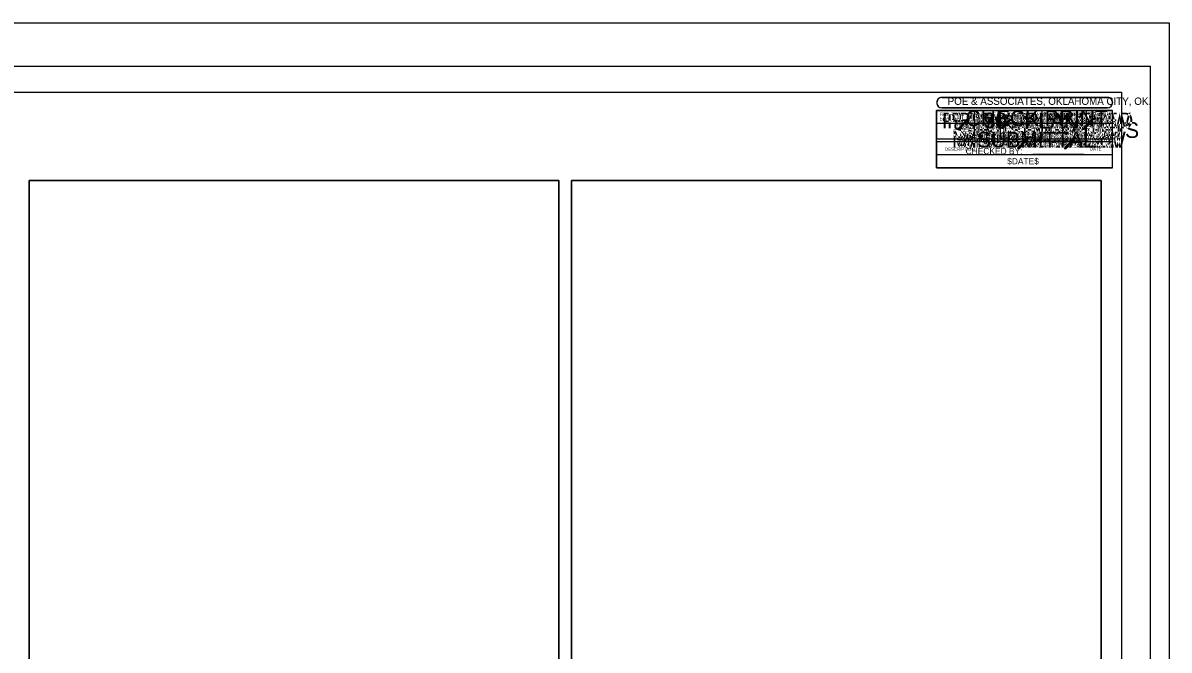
# Model space of a CAD drawing. Extents: x -1.6 to 34.4, y -1.2 to 22.8.
# Drawn here: x 12.44 to 34.36, y 10.82 to 22.82 of the extents above; entities that cross this region are included whole.
import ezdxf

# ---------------------------------------------------------------- set-up
doc = ezdxf.new("R2010")
doc.units = 0
for name, color, linetype in [('PR_OLE_MS_Excel', 7, 'Continuous'), ('SHT_Date_Stamp', 7, 'Continuous'), ('SHT_Plot_Shape_Full', 7, 'Continuous'), ('SHT_Plot_Shape_Half', 7, 'Continuous'), ('SHT_Sheet_Border', 7, 'Continuous'), ('SHT_Stamp_30_Submit', 7, 'Continuous'), ('SHT_Stamp_70_Submit', 7, 'Continuous'), ('SHT_Stamp_90_Submit', 7, 'Continuous'), ('SHT_Stamp_Check_Print', 7, 'Continuous'), ('SHT_Stamp_Est_Inf', 7, 'Continuous'), ('SHT_Stamp_FFR', 7, 'Continuous'), ('SHT_Stamp_Info_Material', 7, 'Continuous'), ('SHT_Stamp_No_Const', 7, 'Continuous'), ('SHT_Stamp_No_Design', 7, 'Continuous'), ('SHT_Stamp_Plan_Hand', 7, 'Continuous'), ('SHT_Stamp_Pre_Plan', 7, 'Continuous'), ('SHT_Stamp_Prop_RW', 7, 'Continuous'), ('SHT_Stamp_Ret_Sub', 7, 'Continuous'), ('SHT_Stamp_Rev_Block', 7, 'Continuous'), ('SHT_Stamp_Rev_Prop_RW', 7, 'Continuous'), ('SHT_Stamp_Rev_Sheet', 7, 'Continuous'), ('SHT_Stamp_RW_Utilities_Meeting', 7, 'Continuous'), ('SHT_Stamp_RW_Utilities_Review', 7, 'Continuous'), ('SHT_Stamp_Send_Comments', 7, 'Continuous')]:
    doc.layers.add(name, color=color, linetype=linetype)

msp = doc.modelspace()

# ---------------------------------------------------------------- linework, layer by layer
at = {"layer": 'PR_OLE_MS_Excel'}
for points in [[(12.56, 19.811), (22.69, 19.811), (22.69, 3.188), (12.56, 3.188)], [(12.56, 3.188), (22.69, 3.188), (22.69, 19.811), (12.56, 19.811)], [(22.93, 19.811), (33.061, 19.811), (33.061, 6.46), (22.93, 6.46)], [(22.93, 6.46), (33.061, 6.46), (33.061, 19.811), (22.93, 19.811)]]:
    msp.add_lwpolyline(points, close=True, dxfattribs=at)
at = {"layer": 'SHT_Plot_Shape_Full'}
msp.add_lwpolyline([(-1.638, 22.825), (34.362, 22.825), (34.362, -1.175), (-1.638, -1.175)], close=True, dxfattribs=at)
at = {"layer": 'SHT_Plot_Shape_Half'}
msp.add_lwpolyline([(0, 22), (34, 22), (34, 0), (0, 0)], close=True, dxfattribs=at)
at = {"layer": 'SHT_Sheet_Border'}
msp.add_lwpolyline([(33.45, 0.5), (1.95, 0.5), (1.95, 21.5), (33.45, 21.5)], close=True, dxfattribs=at)
at = {"layer": 'SHT_Stamp_30_Submit'}
for p, q in [((30.017, 21.4), (33.183, 21.4)), ((29.917, 21.15), (33.283, 21.15)), ((29.917, 20.051), (29.917, 21.15)), ((30.017, 21.2), (33.183, 21.2)), ((33.283, 20.051), (33.283, 21.15)), ((31.161, 20.812), (31.316, 20.984)), ((31.178, 20.812), (31.334, 20.984)), ((31.183, 20.812), (31.339, 20.984)), ((31.191, 20.812), (31.347, 20.984)), ((31.316, 20.984), (31.347, 20.984)), ((31.161, 20.812), (31.191, 20.812)), ((29.917, 20.051), (33.283, 20.051))]:
    msp.add_line(p, q, dxfattribs=at)
for centre, start, end in [((30.018, 21.3), 89.9952, 270), ((33.184, 21.3), 270, 90.0048)]:
    msp.add_arc(centre, 0.1, start, end, dxfattribs=at)
at = {"layer": 'SHT_Stamp_70_Submit'}
for p, q in [((30.017, 21.4), (33.183, 21.4)), ((29.917, 21.15), (33.283, 21.15)), ((29.917, 20.051), (29.917, 21.15)), ((30.017, 21.2), (33.183, 21.2)), ((33.283, 20.051), (33.283, 21.15)), ((31.161, 20.812), (31.316, 20.984)), ((31.178, 20.812), (31.334, 20.984)), ((31.183, 20.812), (31.339, 20.984)), ((31.191, 20.812), (31.347, 20.984)), ((31.316, 20.984), (31.347, 20.984)), ((31.161, 20.812), (31.191, 20.812)), ((29.917, 20.051), (33.283, 20.051))]:
    msp.add_line(p, q, dxfattribs=at)
for centre, start, end in [((30.018, 21.3), 89.9952, 270), ((33.184, 21.3), 270, 90.0048)]:
    msp.add_arc(centre, 0.1, start, end, dxfattribs=at)
at = {"layer": 'SHT_Stamp_90_Submit'}
for p, q in [((30.017, 21.4), (33.183, 21.4)), ((29.917, 21.15), (33.283, 21.15)), ((29.917, 20.051), (29.917, 21.15)), ((30.017, 21.2), (33.183, 21.2)), ((33.283, 20.051), (33.283, 21.15)), ((31.161, 20.812), (31.316, 20.984)), ((31.178, 20.812), (31.334, 20.984)), ((31.183, 20.812), (31.339, 20.984)), ((31.191, 20.812), (31.347, 20.984)), ((31.316, 20.984), (31.347, 20.984)), ((31.161, 20.812), (31.191, 20.812)), ((29.917, 20.051), (33.283, 20.051))]:
    msp.add_line(p, q, dxfattribs=at)
for centre, start, end in [((30.018, 21.3), 89.9952, 270), ((33.184, 21.3), 270, 90.0048)]:
    msp.add_arc(centre, 0.1, start, end, dxfattribs=at)
at = {"layer": 'SHT_Stamp_Check_Print'}
for p, q in [((30.017, 21.4), (33.183, 21.4)), ((29.917, 21.15), (33.283, 21.15)), ((29.917, 20.051), (29.917, 21.15)), ((30.017, 21.2), (33.183, 21.2)), ((33.283, 20.051), (33.283, 21.15)), ((31.759, 20.569), (32.73, 20.569)), ((31.759, 20.313), (32.73, 20.313)), ((29.917, 20.051), (33.283, 20.051))]:
    msp.add_line(p, q, dxfattribs=at)
for centre, start, end in [((30.018, 21.3), 89.9952, 270), ((33.184, 21.3), 270, 90.0048)]:
    msp.add_arc(centre, 0.1, start, end, dxfattribs=at)
at = {"layer": 'SHT_Stamp_Est_Inf'}
for p, q in [((30.017, 21.4), (33.183, 21.4)), ((29.917, 21.15), (33.283, 21.15)), ((29.917, 20.051), (29.917, 21.15)), ((30.017, 21.2), (33.183, 21.2)), ((33.283, 20.051), (33.283, 21.15)), ((29.917, 20.051), (33.283, 20.051))]:
    msp.add_line(p, q, dxfattribs=at)
for centre, start, end in [((30.018, 21.3), 89.9952, 270), ((33.184, 21.3), 270, 90.0048)]:
    msp.add_arc(centre, 0.1, start, end, dxfattribs=at)
at = {"layer": 'SHT_Stamp_FFR'}
for p, q in [((30.017, 21.4), (33.183, 21.4)), ((29.917, 21.15), (33.283, 21.15)), ((29.917, 20.051), (29.917, 21.15)), ((30.017, 21.2), (33.183, 21.2)), ((33.283, 20.051), (33.283, 21.15)), ((29.917, 20.051), (33.283, 20.051))]:
    msp.add_line(p, q, dxfattribs=at)
for centre, start, end in [((30.018, 21.3), 89.9952, 270), ((33.184, 21.3), 270, 90.0048)]:
    msp.add_arc(centre, 0.1, start, end, dxfattribs=at)
at = {"layer": 'SHT_Stamp_Info_Material'}
for p, q in [((30.017, 21.4), (33.183, 21.4)), ((29.917, 21.15), (33.283, 21.15)), ((29.917, 20.051), (29.917, 21.15)), ((30.017, 21.2), (33.183, 21.2)), ((33.283, 20.051), (33.283, 21.15)), ((29.917, 20.051), (33.283, 20.051))]:
    msp.add_line(p, q, dxfattribs=at)
for centre, start, end in [((30.018, 21.3), 89.9952, 270), ((33.184, 21.3), 270, 90.0048)]:
    msp.add_arc(centre, 0.1, start, end, dxfattribs=at)
at = {"layer": 'SHT_Stamp_No_Const'}
for p, q in [((30.017, 21.4), (33.183, 21.4)), ((29.917, 21.15), (33.283, 21.15)), ((29.917, 20.051), (29.917, 21.15)), ((30.017, 21.2), (33.183, 21.2)), ((33.283, 20.051), (33.283, 21.15)), ((29.917, 20.051), (33.283, 20.051))]:
    msp.add_line(p, q, dxfattribs=at)
for centre, start, end in [((30.018, 21.3), 89.9952, 270), ((33.184, 21.3), 270, 90.0048)]:
    msp.add_arc(centre, 0.1, start, end, dxfattribs=at)
at = {"layer": 'SHT_Stamp_No_Design'}
for p, q in [((30.017, 21.4), (33.183, 21.4)), ((29.917, 21.15), (33.283, 21.15)), ((29.917, 20.051), (29.917, 21.15)), ((30.017, 21.2), (33.183, 21.2)), ((33.283, 20.051), (33.283, 21.15)), ((29.917, 20.051), (33.283, 20.051))]:
    msp.add_line(p, q, dxfattribs=at)
for centre, start, end in [((30.018, 21.3), 89.9952, 270), ((33.184, 21.3), 270, 90.0048)]:
    msp.add_arc(centre, 0.1, start, end, dxfattribs=at)
at = {"layer": 'SHT_Stamp_Plan_Hand'}
for p, q in [((30.017, 21.4), (33.183, 21.4)), ((29.917, 21.15), (33.283, 21.15)), ((29.917, 20.051), (29.917, 21.15)), ((30.017, 21.2), (33.183, 21.2)), ((33.283, 20.051), (33.283, 21.15)), ((29.917, 20.051), (33.283, 20.051))]:
    msp.add_line(p, q, dxfattribs=at)
for centre, start, end in [((30.018, 21.3), 89.9952, 270), ((33.184, 21.3), 270, 90.0048)]:
    msp.add_arc(centre, 0.1, start, end, dxfattribs=at)
at = {"layer": 'SHT_Stamp_Pre_Plan'}
for p, q in [((30.017, 21.4), (33.183, 21.4)), ((29.917, 21.15), (33.283, 21.15)), ((29.917, 20.051), (29.917, 21.15)), ((30.017, 21.2), (33.183, 21.2)), ((33.283, 20.051), (33.283, 21.15)), ((29.917, 20.051), (33.283, 20.051))]:
    msp.add_line(p, q, dxfattribs=at)
for centre, start, end in [((30.018, 21.3), 89.9952, 270), ((33.184, 21.3), 270, 90.0048)]:
    msp.add_arc(centre, 0.1, start, end, dxfattribs=at)
at = {"layer": 'SHT_Stamp_Prop_RW'}
for p, q in [((30.017, 21.4), (33.183, 21.4)), ((30.017, 21.4), (33.183, 21.4)), ((29.917, 21.15), (33.283, 21.15)), ((29.917, 20.051), (29.917, 21.15)), ((29.917, 21.15), (33.283, 21.15)), ((29.917, 20.051), (29.917, 21.15)), ((30.017, 21.2), (33.183, 21.2)), ((30.017, 21.2), (33.183, 21.2)), ((33.283, 20.051), (33.283, 21.15)), ((33.283, 20.051), (33.283, 21.15)), ((31.464, 20.423), (31.656, 20.636)), ((31.464, 20.423), (31.656, 20.636)), ((31.486, 20.423), (31.678, 20.636)), ((31.486, 20.423), (31.678, 20.636)), ((31.492, 20.423), (31.684, 20.636)), ((31.492, 20.423), (31.684, 20.636)), ((31.502, 20.423), (31.694, 20.636)), ((31.502, 20.423), (31.694, 20.636)), ((31.656, 20.636), (31.694, 20.636)), ((31.656, 20.636), (31.694, 20.636)), ((31.464, 20.423), (31.502, 20.423)), ((31.464, 20.423), (31.502, 20.423)), ((29.917, 20.051), (33.283, 20.051)), ((29.917, 20.051), (33.283, 20.051))]:
    msp.add_line(p, q, dxfattribs=at)
for centre, start, end in [((30.018, 21.3), 89.9952, 270), ((30.018, 21.3), 89.9952, 270), ((33.184, 21.3), 270, 90.0048), ((33.184, 21.3), 270, 90.0048)]:
    msp.add_arc(centre, 0.1, start, end, dxfattribs=at)
at = {"layer": 'SHT_Stamp_Ret_Sub'}
for p, q in [((30.017, 21.4), (33.183, 21.4)), ((29.917, 21.15), (33.283, 21.15)), ((29.917, 20.051), (29.917, 21.15)), ((30.017, 21.2), (33.183, 21.2)), ((33.283, 20.051), (33.283, 21.15)), ((29.917, 20.051), (33.283, 20.051))]:
    msp.add_line(p, q, dxfattribs=at)
for centre, start, end in [((30.018, 21.3), 89.9952, 270), ((33.184, 21.3), 270, 90.0048)]:
    msp.add_arc(centre, 0.1, start, end, dxfattribs=at)
at = {"layer": 'SHT_Stamp_Rev_Block'}
for p, q in [((33.183, 21.4), (30.018, 21.4)), ((33.283, 21.15), (29.917, 21.15)), ((29.917, 21.15), (29.917, 20.6)), ((33.183, 21.2), (30.018, 21.2)), ((30.633, 21.15), (30.633, 20.6)), ((31.133, 21.15), (31.133, 20.6)), ((31.933, 20.6), (31.933, 21.15)), ((32.333, 20.6), (32.333, 21.15)), ((32.783, 20.6), (32.783, 21.15)), ((33.283, 20.6), (33.283, 21.15)), ((33.283, 20.9), (29.917, 20.9)), ((33.283, 20.6), (29.917, 20.6)), ((33.283, 20.55), (29.917, 20.55)), ((29.917, 20.55), (29.917, 20.05)), ((33.283, 20.05), (33.283, 20.55)), ((33.283, 20.3), (29.917, 20.3)), ((33.283, 20.05), (29.917, 20.05))]:
    msp.add_line(p, q, dxfattribs=at)
for centre, start, end in [((30.018, 21.299), 90, 270), ((33.183, 21.3), 270, 90)]:
    msp.add_arc(centre, 0.1, start, end, dxfattribs=at)
at = {"layer": 'SHT_Stamp_Rev_Prop_RW'}
for p, q in [((30.017, 21.4), (33.183, 21.4)), ((29.917, 21.15), (33.283, 21.15)), ((29.917, 20.051), (29.917, 21.15)), ((30.017, 21.2), (33.183, 21.2)), ((33.283, 20.051), (33.283, 21.15)), ((32.354, 20.42), (32.546, 20.633)), ((32.376, 20.42), (32.568, 20.633)), ((32.383, 20.42), (32.575, 20.633)), ((32.392, 20.42), (32.584, 20.633)), ((32.546, 20.633), (32.584, 20.633)), ((32.354, 20.42), (32.392, 20.42)), ((29.917, 20.051), (33.283, 20.051))]:
    msp.add_line(p, q, dxfattribs=at)
for centre, start, end in [((30.018, 21.3), 89.9952, 270), ((33.184, 21.3), 270, 90.0048)]:
    msp.add_arc(centre, 0.1, start, end, dxfattribs=at)
at = {"layer": 'SHT_Stamp_Rev_Sheet'}
for p, q in [((30.017, 21.4), (33.183, 21.4)), ((29.917, 21.15), (33.283, 21.15)), ((29.917, 20.051), (29.917, 21.15)), ((30.017, 21.2), (33.183, 21.2)), ((33.283, 20.051), (33.283, 21.15)), ((29.917, 20.051), (33.283, 20.051))]:
    msp.add_line(p, q, dxfattribs=at)
for centre, start, end in [((30.018, 21.3), 89.9952, 270), ((33.184, 21.3), 270, 90.0048)]:
    msp.add_arc(centre, 0.1, start, end, dxfattribs=at)
at = {"layer": 'SHT_Stamp_RW_Utilities_Meeting'}
for p, q in [((30.017, 21.4), (33.183, 21.4)), ((29.917, 21.15), (33.283, 21.15)), ((29.917, 20.051), (29.917, 21.15)), ((30.017, 21.2), (33.183, 21.2)), ((33.283, 20.051), (33.283, 21.15)), ((30.319, 20.789), (30.511, 21.003)), ((30.341, 20.789), (30.533, 21.003)), ((30.348, 20.789), (30.54, 21.003)), ((30.357, 20.789), (30.549, 21.003)), ((30.511, 21.003), (30.549, 21.003)), ((30.319, 20.789), (30.357, 20.789)), ((29.917, 20.051), (33.283, 20.051))]:
    msp.add_line(p, q, dxfattribs=at)
for centre, start, end in [((30.018, 21.3), 89.9952, 270), ((33.184, 21.3), 270, 90.0048)]:
    msp.add_arc(centre, 0.1, start, end, dxfattribs=at)
at = {"layer": 'SHT_Stamp_RW_Utilities_Review'}
for p, q in [((30.017, 21.4), (33.183, 21.4)), ((29.917, 21.15), (33.283, 21.15)), ((29.917, 20.051), (29.917, 21.15)), ((30.017, 21.2), (33.183, 21.2)), ((33.283, 20.051), (33.283, 21.15)), ((32.708, 20.789), (32.9, 21.003)), ((32.73, 20.789), (32.922, 21.003)), ((32.736, 20.789), (32.928, 21.003)), ((32.746, 20.789), (32.938, 21.003)), ((32.9, 21.003), (32.938, 21.003)), ((32.708, 20.789), (32.746, 20.789)), ((29.917, 20.051), (33.283, 20.051))]:
    msp.add_line(p, q, dxfattribs=at)
for centre, start, end in [((30.018, 21.3), 89.9952, 270), ((33.184, 21.3), 270, 90.0048)]:
    msp.add_arc(centre, 0.1, start, end, dxfattribs=at)
at = {"layer": 'SHT_Stamp_Send_Comments'}
for p, q in [((30.017, 21.4), (33.183, 21.4)), ((29.917, 21.15), (33.283, 21.15)), ((29.917, 20.051), (29.917, 21.15)), ((30.017, 21.2), (33.183, 21.2)), ((33.283, 20.051), (33.283, 21.15)), ((29.917, 20.051), (33.283, 20.051))]:
    msp.add_line(p, q, dxfattribs=at)
for centre, start, end in [((30.018, 21.3), 89.9952, 270), ((33.184, 21.3), 270, 90.0048)]:
    msp.add_arc(centre, 0.1, start, end, dxfattribs=at)

# ---------------------------------------------------------------- texts
at = {"layer": 'SHT_Date_Stamp'}
msp.add_text('$DATE$', height=0.12, dxfattribs=at).set_placement((31.266, 20.119))
at = {"layer": 'SHT_Stamp_30_Submit'}
for s, height, p in [('POE & ASSOCIATES, OKLAHOMA CITY, OK.', 0.14, (30.127, 21.257)), ('30   PLAN', 0.3, (30.82, 20.808)), ('O', 0.153, (31.126, 20.897)), ('O', 0.153, (31.278, 20.812)), ('SUBMITTAL', 0.3, (30.689, 20.441))]:
    msp.add_text(s, height=height, dxfattribs=at).set_placement(p)
at = {"layer": 'SHT_Stamp_70_Submit'}
for s, height, p in [('POE & ASSOCIATES, OKLAHOMA CITY, OK.', 0.14, (30.127, 21.257)), ('70   PLAN', 0.3, (30.813, 20.808)), ('O', 0.153, (31.126, 20.897)), ('O', 0.153, (31.278, 20.812)), ('SUBMITTAL', 0.3, (30.689, 20.441))]:
    msp.add_text(s, height=height, dxfattribs=at).set_placement(p)
at = {"layer": 'SHT_Stamp_90_Submit'}
for s, height, p in [('POE & ASSOCIATES, OKLAHOMA CITY, OK.', 0.14, (30.127, 21.257)), ('90   PLAN', 0.3, (30.813, 20.808)), ('O', 0.153, (31.126, 20.897)), ('O', 0.153, (31.278, 20.812)), ('SUBMITTAL', 0.3, (30.689, 20.441))]:
    msp.add_text(s, height=height, dxfattribs=at).set_placement(p)
at = {"layer": 'SHT_Stamp_Check_Print'}
for s, height, p in [('POE & ASSOCIATES, OKLAHOMA CITY, OK.', 0.14, (30.128, 21.258)), ('CHECK PRINT', 0.3, (30.47, 20.851)), ('REVISED BY:', 0.12, (30.471, 20.568)), ('CHECKED BY:', 0.12, (30.471, 20.313))]:
    msp.add_text(s, height=height, dxfattribs=at).set_placement(p)
at = {"layer": 'SHT_Stamp_Est_Inf'}
for s, height, p in [('POE & ASSOCIATES, OKLAHOMA CITY, OK.', 0.14, (30.128, 21.258)), ('BASED ON EST.', 0.3, (30.348, 20.808)), ('INFORMATION', 0.3, (30.47, 20.441))]:
    msp.add_text(s, height=height, dxfattribs=at).set_placement(p)
at = {"layer": 'SHT_Stamp_FFR'}
for s, height, p in [('POE & ASSOCIATES, OKLAHOMA CITY, OK.', 0.14, (30.128, 21.258)), ('FINAL FIELD', 0.3, (30.569, 20.808)), ('REVIEW', 0.3, (30.997, 20.441))]:
    msp.add_text(s, height=height, dxfattribs=at).set_placement(p)
at = {"layer": 'SHT_Stamp_Info_Material'}
for s, height, p in [('POE & ASSOCIATES, OKLAHOMA CITY, OK.', 0.14, (30.128, 21.258)), ('INFORMATION', 0.3, (30.47, 20.808)), ('MATERIAL ONLY', 0.3, (30.211, 20.441))]:
    msp.add_text(s, height=height, dxfattribs=at).set_placement(p)
at = {"layer": 'SHT_Stamp_No_Const'}
for s, height, p in [('POE & ASSOCIATES, OKLAHOMA CITY, OK.', 0.14, (30.128, 21.258)), ('NOT TO BE USED', 0.3, (30.158, 20.808)), ('FOR CONST.', 0.3, (30.648, 20.441))]:
    msp.add_text(s, height=height, dxfattribs=at).set_placement(p)
at = {"layer": 'SHT_Stamp_No_Design'}
for s, height, p in [('POE & ASSOCIATES, OKLAHOMA CITY, OK.', 0.14, (30.128, 21.258)), ('NOT TO BE USED', 0.3, (30.158, 20.808)), ('FOR DESIGN', 0.3, (30.631, 20.441))]:
    msp.add_text(s, height=height, dxfattribs=at).set_placement(p)
at = {"layer": 'SHT_Stamp_Plan_Hand'}
for s, height, p in [('POE & ASSOCIATES, OKLAHOMA CITY, OK.', 0.14, (30.128, 21.258)), ('PLAN-IN-HAND', 0.3, (30.402, 20.625))]:
    msp.add_text(s, height=height, dxfattribs=at).set_placement(p)
at = {"layer": 'SHT_Stamp_Pre_Plan'}
for s, height, p in [('POE & ASSOCIATES, OKLAHOMA CITY, OK.', 0.14, (30.128, 21.258)), ('PRELIMINARY', 0.3, (30.485, 20.808)), ('PLANS', 0.3, (31.093, 20.441))]:
    msp.add_text(s, height=height, dxfattribs=at).set_placement(p)
at = {"layer": 'SHT_Stamp_Prop_RW'}
for s, height, p in [('POE & ASSOCIATES, OKLAHOMA CITY, OK.', 0.14, (30.128, 21.258)), ('POE & ASSOCIATES, OKLAHOMA CITY, OK.', 0.14, (30.128, 21.258)), ('PROPOSED', 0.3, (30.827, 20.808)), ('PROPOSED', 0.3, (30.827, 20.808)), ('R W', 0.3, (31.259, 20.441)), ('R W', 0.3, (31.259, 20.441))]:
    msp.add_text(s, height=height, dxfattribs=at).set_placement(p)
at = {"layer": 'SHT_Stamp_Ret_Sub'}
for s, height, p in [('POE & ASSOCIATES, OKLAHOMA CITY, OK.', 0.14, (30.128, 21.258)), ('RET. SUBMITTED', 0.3, (30.335, 20.808)), ('MATERIALS', 0.3, (30.677, 20.441))]:
    msp.add_text(s, height=height, dxfattribs=at).set_placement(p)
at = {"layer": 'SHT_Stamp_Rev_Block'}
for s, height, p in [('POE & ASSOCIATES, OKLAHOMA CITY, OK.', 0.14, (30.128, 21.258)), ('FED.  ROAD', 0.06, (29.973, 21.045)), ('STATE', 0.06, (30.746, 20.995)), ('JOB PIECE NO.', 0.06, (31.165, 20.995)), ('FISCAL', 0.06, (31.966, 21.045)), ('SHEET', 0.06, (32.421, 21.045)), ('TOTAL', 0.06, (32.896, 21.045)), ('DIST.  NO.', 0.06, (29.973, 20.949)), ('YEAR', 0.06, (32.025, 20.949)), ('NO.', 0.06, (32.48, 20.945)), ('SHEETS', 0.06, (32.865, 20.949)), ('6', 0.08, (30.233, 20.71)), ('OKLA.', 0.08, (30.7, 20.71)), ('DESCRIPTION', 0.06, (30.077, 20.378)), ('REVISIONS', 0.06, (31.326, 20.437)), ('DATE', 0.06, (32.847, 20.382))]:
    msp.add_text(s, height=height, dxfattribs=at).set_placement(p)
at = {"layer": 'SHT_Stamp_Rev_Prop_RW'}
for s, height, p in [('POE & ASSOCIATES, OKLAHOMA CITY, OK.', 0.14, (30.128, 21.258)), ('REVISED', 0.3, (30.954, 20.808)), ('PROPOSED R W', 0.3, (30.369, 20.441))]:
    msp.add_text(s, height=height, dxfattribs=at).set_placement(p)
at = {"layer": 'SHT_Stamp_Rev_Sheet'}
for s, height, p in [('POE & ASSOCIATES, OKLAHOMA CITY, OK.', 0.14, (30.128, 21.258)), ('REVISED SHEET', 0.3, (30.352, 20.625))]:
    msp.add_text(s, height=height, dxfattribs=at).set_placement(p)
at = {"layer": 'SHT_Stamp_RW_Utilities_Meeting'}
for s, height, p in [('POE & ASSOCIATES, OKLAHOMA CITY, OK.', 0.14, (30.127, 21.257)), ('R W & UTILITIES', 0.3, (30.112, 20.808)), ('MEETING', 0.3, (30.881, 20.441))]:
    msp.add_text(s, height=height, dxfattribs=at).set_placement(p)
at = {"layer": 'SHT_Stamp_RW_Utilities_Review'}
for s, height, p in [('POE & ASSOCIATES, OKLAHOMA CITY, OK.', 0.14, (30.127, 21.257)), ('PRELIMINARY R W', 0.3, (30.017, 20.808)), ('& UTIL.  REVIEW', 0.3, (30.3, 20.441))]:
    msp.add_text(s, height=height, dxfattribs=at).set_placement(p)
at = {"layer": 'SHT_Stamp_Send_Comments'}
for s, height, p in [('POE & ASSOCIATES, OKLAHOMA CITY, OK.', 0.14, (30.128, 21.258)), ('SEND COMMENTS', 0.3, (30.223, 20.625))]:
    msp.add_text(s, height=height, dxfattribs=at).set_placement(p)

doc.saveas('drawing.dxf')
